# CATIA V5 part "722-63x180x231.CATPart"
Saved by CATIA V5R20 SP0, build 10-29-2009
Part number: 722-63x180x231
Definition: NONE
Nomenclature: 722-63x180x231
Source: Unknown
Description: 722-63x180x231
Bounding box of the stored display mesh (mm): x -31.5 to 31.5, y -31.5 to 31.5, z -162 to 69
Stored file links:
  C:\Users\Utente\Desktop\IO LAVORO\3D X SITO CF\X SITO\722\722-63x180x231.CATPart
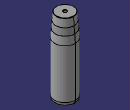
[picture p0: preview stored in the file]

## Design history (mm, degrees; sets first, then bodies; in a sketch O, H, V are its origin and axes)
Body1 "722-63x180x231" (main body)
  Solid1: solid without history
